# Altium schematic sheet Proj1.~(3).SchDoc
size A4
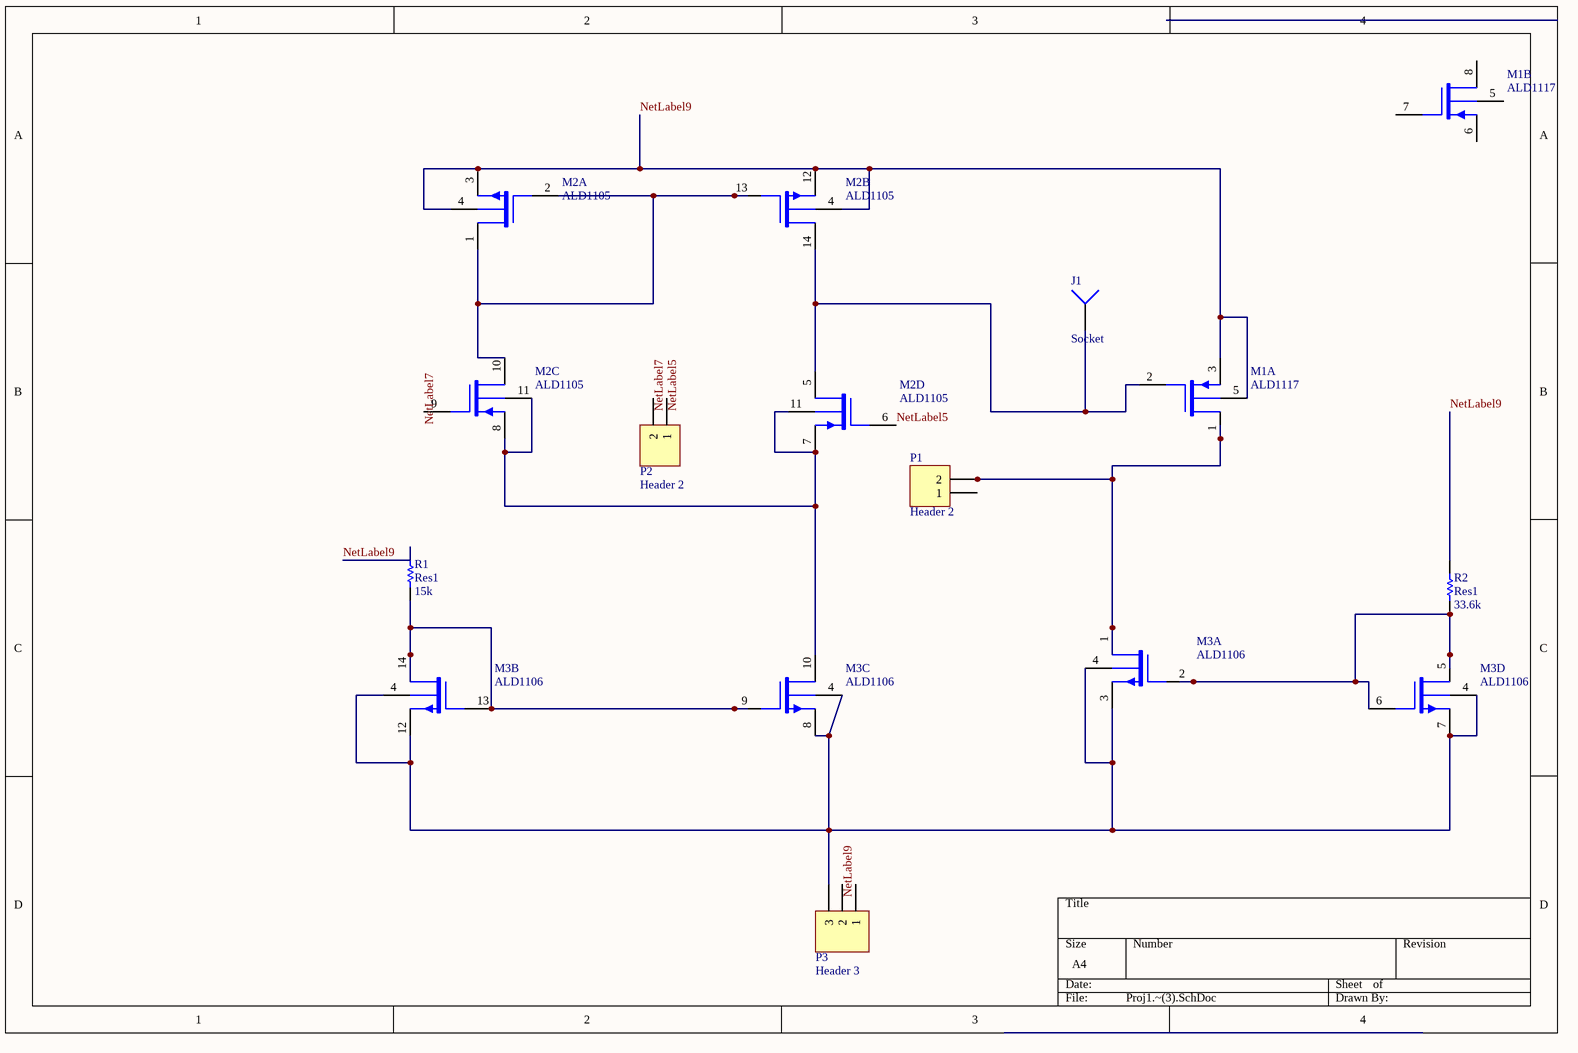
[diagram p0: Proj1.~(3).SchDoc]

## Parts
J1  Socket  [PIN1]
M1  ALD1117  [DIP-8]  (parts A,B of 2)
M2  ALD1105  [DIP-14]  (parts A,B,C,D of 4)
M3  ALD1106  [DIP-14]  (parts A,B,C,D of 4)
P1  Header 2  [HDR1X2]
P2  Header 2  [HDR1X2]
P3  Header 3  [HDR1X3]
R1  Res1  value 15k  [AXIAL-0.3]
R2  Res1  value 33.6k  [AXIAL-0.3]

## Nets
NetLabel5: M2.6(GP1)
NetLabel9: M1.3(SP1) M1.5(V+) M2.3(SN1) M2.4(V-) M2.12(SN2) R1.2 R2.2
NetJ1_1: J1.1 M1.2(GP1) M2.5(DP1) M2.14(DN2)
NetM1_1: M1.1(DP1) M3.1(DN1) P1.2
NetM2_1: M2.1(DN1) M2.2(GN1) M2.10(DP2) M2.13(GN2)
NetM2_7: M2.7(SP1) M2.8(SP2) M2.11(V+) M3.10(DN3)
NetM3_2: M3.2(GN1) M3.5(DN4) M3.6(GN4) R2.1
NetM3_3: M3.3(SN1) M3.4(V-) M3.7(SN4) M3.8(SN3) M3.12(SN2) P3.3
NetM3_9: M3.9(GN3) M3.13(GN2) M3.14(DN2) R1.1

Not connected (* = marked no-connect by the designer): M1 6(SP2) 7(GP2) 8(DP2); M2 9(GP2); P1 1; P2 1 2; P3 1 2

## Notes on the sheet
- Labels drawn without touching a wire or pin: NetLabel5, NetLabel7, NetLabel9

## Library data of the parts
M1 = ALD1117: Dual P-channel matched MOSFET array
M2 = ALD1105: Dual P-channel and dual N-channel matched MOSFET array
M3 = ALD1106: Quad N-channel matched MOSFET array
P1 P2 = Header 2: Header, 2-Pin
P3 = Header 3: Header, 3-Pin
R1 R2 = Res1: Resistor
